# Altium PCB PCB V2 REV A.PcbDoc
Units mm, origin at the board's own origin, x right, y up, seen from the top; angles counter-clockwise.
Board outline 15.75 x 43.09 mm, 2 copper layers (Top, Bot), stack 1.606 mm thick; 8 components, 22 nets, 18 pads, 0 vias.
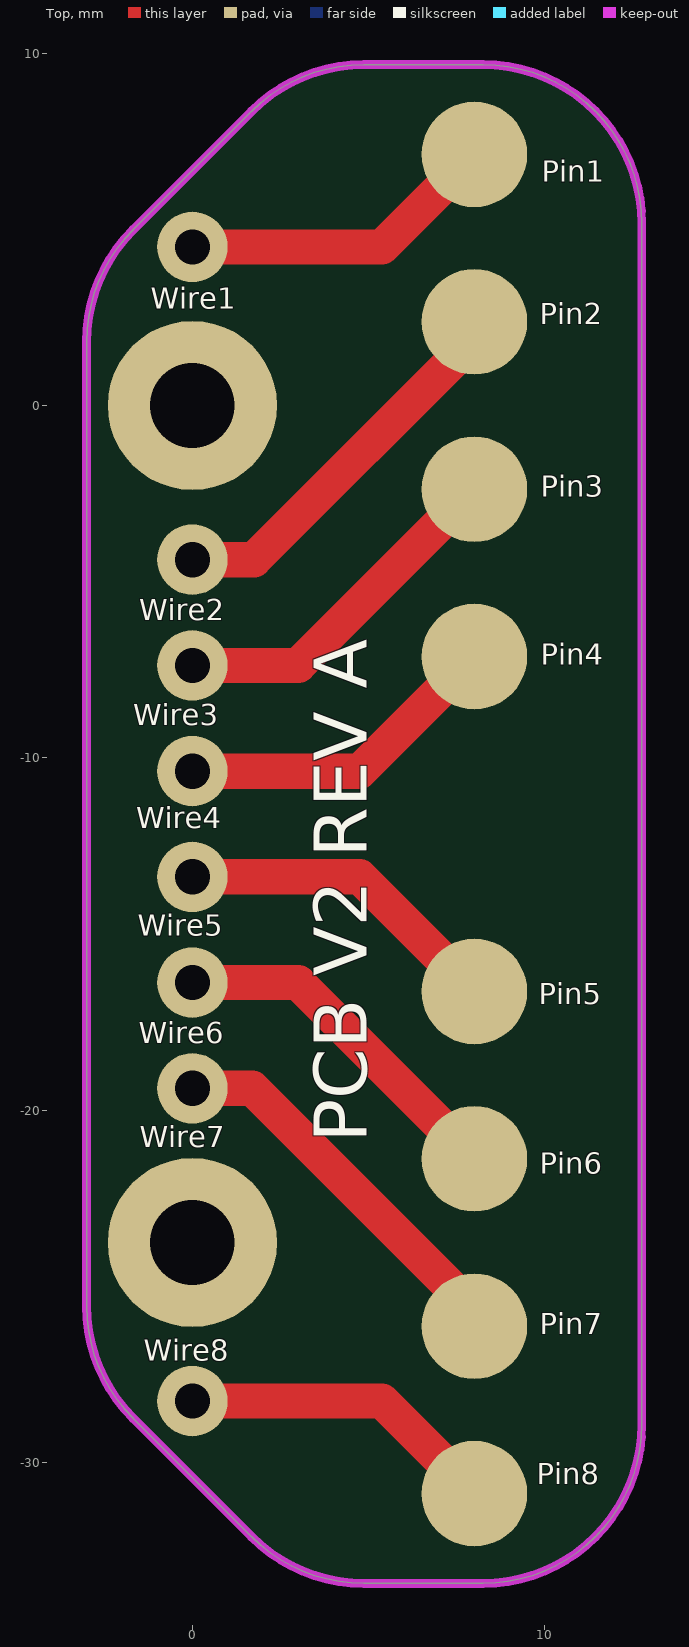
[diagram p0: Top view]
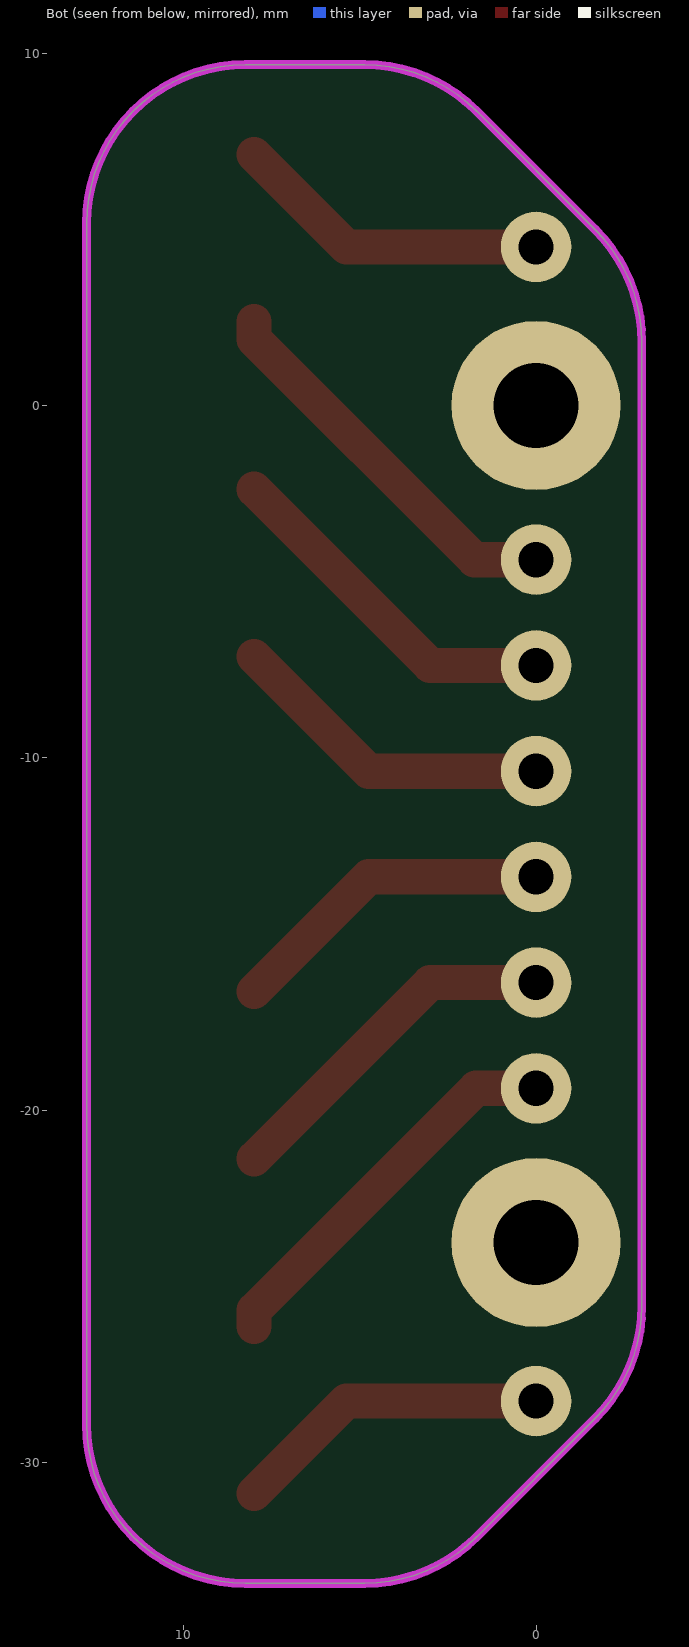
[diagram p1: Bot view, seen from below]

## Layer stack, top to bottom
Top Solder: solder mask 0.0127, Solder Resist, Dk 0
Top: signal copper 0.0178
Dielectric 1: core 1.57, FR4, Dk 4.3
Bot: signal copper 0.0178
Bottom Solder: solder mask 0.0127, Solder Resist, Dk 0

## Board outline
8.25,-33.42 4.864,-33.42 cw(c4.864,-28.92) 1.682,-32.102 -1.682,-28.738 cw(c1.5,-25.556) -3,-25.556 -3,1.806 cw(c1.5,1.806) -1.682,4.988 1.682,8.352 cw(c4.864,5.17) 4.864,9.67 8.25,9.67 cw(c8.25,5.17) 12.75,5.17 12.75,-28.92 cw(c8.25,-28.92)

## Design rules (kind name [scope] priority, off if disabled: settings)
BoardOutlineClearance [All] p1: gap=0.25 except(0: Arc-SplitContinuation Track-SplitContinuation SMDPad-SplitContinuation THPad-SplitContinuation Via-SplitContinuation Fill-SplitContinuation Poly-SplitContinuation Region-SplitContinuation Text-SplitContinuation)
Clearance "Polygon Pour Clearance" [InPolygon] p1: gap=0.85
Clearance [All] p2 off: gap=0.2
ComponentClearance [All] p1: gap=0.1 collisioncheckmode=3 verticalgap=0.1 showdistances=FALSE
DiffPairsRouting DiffPair_100DiffPairsRouting [InDifferentialPairClass('DIFF100')] p1: maxlimit=0.6 minlimit=0.25 mostfreqgap=0.5 toplayer_minwidth=0.25 toplayer_maxwidth=0.35 toplayer_prefwidth=0.3 bottomlayer_minwidth=0.25 bottomlayer_maxwidth=0.35 bottomlayer_prefwidth=0.3 maxuncoupledlength=0
DiffPairsRouting [All] p2: maxlimit=0.254 minlimit=0.254 mostfreqgap=0.254 toplayer_minwidth=0.381 toplayer_maxwidth=0.381 toplayer_prefwidth=0.381 bottomlayer_minwidth=0.381 bottomlayer_maxwidth=0.381 bottomlayer_prefwidth=0.381 maxuncoupledlength=12.7
HoleSize [All] p1: absolutevalues=TRUE maxlimit=50 minlimit=0.3 maxpercent=80.000 minpercent=20.000
HoleToHoleClearance [All] p1: gap=0.25 allowstackedmicrovias=TRUE
MatchedLengths "MatchedLengths USB" [InNetClass('USB')] p1: tolerance=0.1 checknetsindiffpair=FALSE checkdiffpairvsdiffpair=TRUE checkxsignals=TRUE checkothers=TRUE
MatchedLengths DiffPair_100MatchedLengths [InDifferentialPairClass('DIFF100')] p2: tolerance=0.01 checknetsindiffpair=TRUE checkdiffpairvsdiffpair=FALSE checkxsignals=FALSE checkothers=FALSE
MinimumAnnularRing MinimumAnnularRing_VIA [IsVia] p1: minimumring=0.1
MinimumAnnularRing [All] p2: minimumring=0.2
MinimumSolderMaskSliver [All] p1: minsoldermaskwidth=0.025
PlaneClearance [All] p1: clearance=0.3
PlaneConnect [All] p1: planeconnectstyle=Relief reliefexpansion=0.25 reliefentries=4 reliefconductorwidth=0.2 reliefairgap=0.25
PolygonConnect PolygonConnect_RF_GND_VIA [IsVia AND ( InNet('RF1_GND')     OR  InNet('RF2_GND')  )] p1: connectstyle=Direct reliefconductorwidth=0.3 reliefentries=4 polygonreliefangle="90 Angle" airgapwidth=0.3
PolygonConnect PolygonConnect_RF_GND_SH [(InComponent('SH1') AND InNet('RF1_GND') )  OR (InComponent('SH2') AND InNet('RF2_GND') )] p2: connectstyle=Direct reliefconductorwidth=0.3 reliefentries=4 polygonreliefangle="90 Angle" airgapwidth=0.3
PolygonConnect PolygonConnect_NetTieDirect [(InComponent('NT1') OR InComponent('NT2')OR InComponent('NT3') OR InComponent('NT4') OR InComponent('NT5'))] p3: connectstyle=Direct reliefconductorwidth=0.3 reliefentries=4 polygonreliefangle="90 Angle" airgapwidth=0.3
PolygonConnect PolygonConnect_RF_GND [InNet('RF1_GND') OR InNet('RF2_GND')] p4: connectstyle=Relief reliefconductorwidth=0.2 reliefentries=4 polygonreliefangle="90 Angle" airgapwidth=0.2
PolygonConnect [All] p5: connectstyle=Relief reliefconductorwidth=0.2 reliefentries=4 polygonreliefangle="90 Angle" airgapwidth=0.2
RoutingCorners [All] p1: cornerstyle=45-Degree minsetback=2.5 maxsetback=2.5
RoutingVias [All] p1: holewidth=0.305 width=0.61 viastyle="Through Hole" minholewidth=0.305 minwidth=0.61 maxholewidth=0.305 maxwidth=0.61
SilkToSilkClearance [All] p1: silktosilkclearance=0.2
SilkToSolderMaskClearance [IsPad] p1: minsilkscreentomaskgap=0.2 clearancetoexposedcopper=TRUE
SolderMaskExpansion [All] p1: expansion=0.076
Width Width_50OHM [InNetClass('50OHM')] p1: maxlimit=0.3 minlimit=0.229 preferedwidth=0.229 minimp=45.000000 maximp=55.000000 favimp=50.000000
Width [All] p2: maxlimit=5 minlimit=0.15 preferedwidth=0.152 minimp=50.000000 maximp=50.000000 favimp=50.000000
20 further rules are at their usual default settings.

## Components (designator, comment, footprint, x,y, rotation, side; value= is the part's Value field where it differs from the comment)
Pin1 "Comment" "Spring Pin" 8,7.125 r0 top
Pin2 "Comment" "Spring Pin" 8,2.375 r0 top
Pin3 "Comment" "Spring Pin" 8,-2.375 r0 top
Pin4 "Comment" "Spring Pin" 8,-7.125 r0 top
Pin5 "Comment" "Spring Pin" 8,-16.625 r0 top
Pin6 "Comment" "Spring Pin" 8,-21.375 r0 top
Pin7 "Comment" "Spring Pin" 8,-26.125 r0 top
Pin8 "Comment" "Spring Pin" 8,-30.875 r0 top

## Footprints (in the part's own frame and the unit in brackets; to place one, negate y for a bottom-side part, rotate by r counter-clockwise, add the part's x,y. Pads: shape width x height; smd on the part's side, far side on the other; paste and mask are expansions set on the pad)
"Spring Pin" [mm]
  round 3 smd: 1(0,0)

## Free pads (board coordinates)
  round 4.8 hole 2.4: H1(0,0) H2(0,-23.75)
  round 2 hole 1: W1(0,4.5) W2(0,-4.375) W3(0,-7.375) W4(0,-10.375) W5(0,-13.375) W6(0,-16.375) W7(0,-19.375) W8(0,-28.25)

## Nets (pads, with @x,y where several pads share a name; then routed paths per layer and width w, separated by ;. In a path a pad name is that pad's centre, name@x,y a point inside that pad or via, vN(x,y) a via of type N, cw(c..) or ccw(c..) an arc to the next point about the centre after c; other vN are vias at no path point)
+5V_LED: 
GND: 
NetC1_1: 
NetC1_2: 
NetC4_1: 
NetD1_A: 
NetD2_2: 
NetD3_2: 
NetD4_2: 
NetD5_2: 
NetD6_2: 
NetD7_2: 
NetD8_2: 
PWM: 
wire1: pad.W1 Pin1.1 | length 9.1
  Top w1: pad.W1 5.375,4.5 Pin1.1
wire2: pad.W2 Pin2.1 | length 11.1
  Top w1: pad.W2 1.745,-4.375 8,1.88 Pin2.1
wire3: pad.W3 Pin3.1 | length 10.1
  Top w1: pad.W3 3,-7.375 Pin3.1
wire4: pad.W4 Pin4.1 | length 9.3
  Top w1: pad.W4 4.75,-10.375 Pin4.1
wire5: pad.W5 Pin5.1 | length 9.3
  Top w1: pad.W5 4.75,-13.375 Pin5.1
wire6: pad.W6 Pin6.1 | length 10.1
  Top w1: pad.W6 3,-16.375 Pin6.1
wire7: pad.W7 Pin7.1 | length 11.1
  Top w1: pad.W7 1.701,-19.375 8,-25.674 Pin7.1
wire8: pad.W8 Pin8.1 | length 9.1
  Top w1: pad.W8 5.375,-28.25 Pin8.1

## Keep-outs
Keep-Out Layer:
  the board outline again, w0.254

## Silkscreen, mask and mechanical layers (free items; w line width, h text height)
Top Overlay:
  text "Wire1" at -1.184,2.749 h0.6
  text "Wire2" at -1.514,-6.1 h0.6
  text "Wire3" at -1.673,-9.08 h0.6
  text "Wire4" at -1.593,-11.992 h0.6
  text "Wire5" at -1.548,-15.051 h0.6
  text "Wire6" at -1.525,-18.1 h0.6
  text "PCB V2 REV A" at 4.95,-20.914 h1.5 r90
  text "Wire7" at -1.491,-21.045 h0.6
  text "Wire8" at -1.377,-27.108 h0.6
